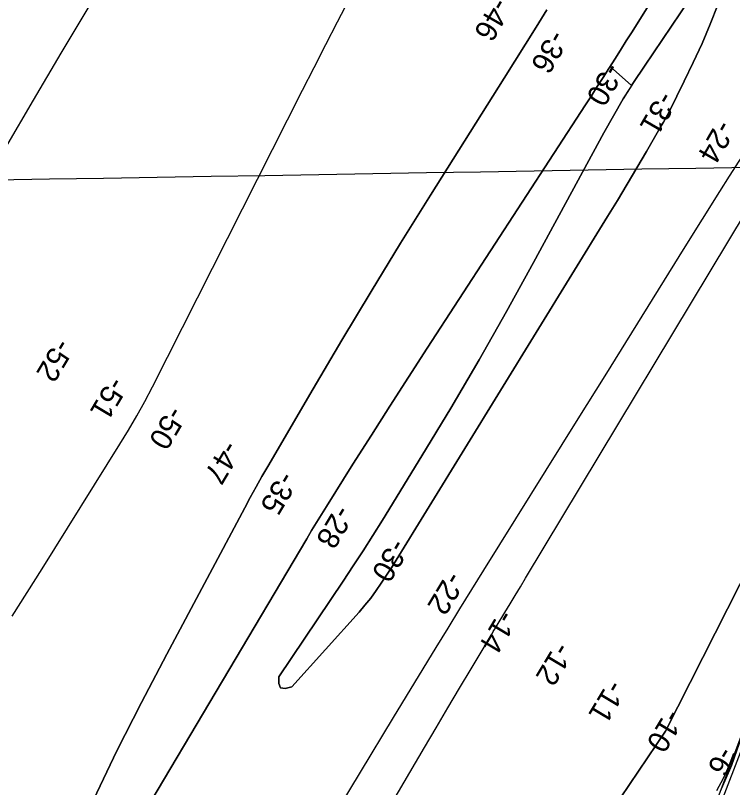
# Model space of a CAD drawing. Extents: x 3888273 to 3909528, y 158682 to 181032.
# Drawn here: x 3899572 to 3900681, y 167939 to 169134 of the extents above; entities that cross this region are included whole.
import ezdxf

# ---------------------------------------------------------------- set-up
doc = ezdxf.new("R2010")
doc.units = 0
for name, color, linetype in [('V-GRID-MAJR', 7, 'Continuous'), ('V-RIVR-JETY', 7, 'Continuous'), ('V-RIVR-RANG', 7, 'Continuous'), ('V-RRAP-FSHR', 7, 'Continuous'), ('V-TOPO-DPTH', 7, 'Continuous'), ('V-TOPO-MAJR', 7, 'Continuous'), ('V-TOPO-MINR', 7, 'Continuous'), ('V-WETL-SWMP', 7, 'Continuous')]:
    doc.layers.add(name, color=color, linetype=linetype)

msp = doc.modelspace()

# ---------------------------------------------------------------- linework, layer by layer
at = {"layer": 'V-GRID-MAJR'}
msp.add_spline([(3893488.4, 168777.6), (3893877.7, 168784.1), (3899208, 168873.7), (3904538.3, 168964), (3905476.7, 168980)], degree=3, dxfattribs=at)
at = {"layer": 'V-RIVR-JETY'}
msp.add_lwpolyline([(3900652.2, 167887.9), (3900673.8, 167944.1), (3900699.3, 168009.2), (3900716.3, 168058), (3900715.7, 168061.2), (3900711.4, 168062), (3900709.8, 168060.9), (3900706.6, 168053.2), (3900678.9, 167973.2), (3900661.4, 167933.3)], dxfattribs=at)
at = {"layer": 'V-RRAP-FSHR'}
msp.add_lwpolyline([(3899996.7, 166588.8), (3900029.7, 166643.4), (3900051.8, 166695.8), (3900145, 166878), (3900473, 167514.6), (3900528.8, 167603.3), (3900571.9, 167693.2), (3900769.5, 168220.1), (3900854, 168410.1), (3901111.7, 168921.3), (3901230.8, 169130.1), (3901232.3, 169133), (3901298.6, 169231.8), (3901395, 169369.5), (3901586, 169601.1), (3901720.2, 169757.4), (3901855.1, 169965.2), (3902076, 170299.4), (3902258.6, 170576), (3902394.3, 170771.7), (3902466.4, 170877.4)], dxfattribs=at)
at = {"layer": 'V-TOPO-DPTH'}
for points in [[(3899237.6, 166978.5), (3899631, 167664.9), (3900022.2, 168324.2), (3900029.7, 168336.7), (3900037.2, 168349.1), (3900044.8, 168361.5), (3900052.5, 168373.8), (3900093.7, 168439.4), (3900122.1, 168484.4), (3900150.6, 168529.3), (3900179.4, 168574.1), (3900208.3, 168618.8), (3900453.3, 168995.5), (3900462.4, 169009.6), (3900471.5, 169023.7), (3900480.5, 169037.8), (3900489.5, 169051.9), (3900498.5, 169066.1), (3900507.4, 169080.2), (3900516.3, 169094.4), (3900525.2, 169108.6), (3900898, 169705.4)], [(3900898, 169705.4), (3900525.2, 169108.6), (3900516.3, 169094.4), (3900507.4, 169080.2), (3900498.5, 169066.1), (3900491.3, 169054.7), (3900524.6, 169025.3)], [(3901523.7, 169550.8), (3901139.1, 169059.9), (3900979.7, 168809.1), (3900964.5, 168784.3), (3900949.7, 168759.3), (3900935.7, 168733.8), (3900922.2, 168708), (3900577.1, 168026.2), (3900117.9, 167345.7), (3899775.5, 166667.7), (3899771.7, 166626.4)], [(3900054.5, 167878.4), (3900105.3, 167962.9), (3900156.4, 168047.4), (3900222.4, 168155.8), (3900240.7, 168185.8), (3900259.1, 168215.9), (3900277.6, 168245.8), (3900296.2, 168275.7), (3900442, 168509.9), (3900483.4, 168576.4), (3900524.8, 168642.9), (3900566.2, 168709.4), (3900607.6, 168775.8), (3900660.8, 168861.2), (3900675.8, 168884.9), (3900690.9, 168908.5), (3900706.4, 168931.9), (3900722.1, 168955.1), (3901022.7, 169328.3)], [(3900054.5, 167878.4), (3900105.3, 167962.9), (3900156.4, 168047.4), (3900222.4, 168155.8), (3900240.7, 168185.8), (3900259.1, 168215.9), (3900277.6, 168245.8), (3900296.2, 168275.7), (3900442, 168509.9), (3900483.4, 168576.4), (3900524.8, 168642.9), (3900566.2, 168709.4), (3900607.6, 168775.8), (3900660.8, 168861.2), (3900675.8, 168884.9), (3900690.9, 168908.5), (3900706.4, 168931.9), (3900722.1, 168955.1), (3901022.7, 169328.3)], [(3900655.6, 169220.6), (3900544.3, 169055.5), (3900527.7, 169030.2), (3900511.6, 169004.5), (3900496.3, 168978.3), (3900481.4, 168951.9), (3900372.9, 168751.4), (3900331.1, 168675.9), (3900288.6, 168600.8), (3900244.9, 168526.3), (3900200.3, 168452.4), (3900139.4, 168353.1), (3900124.6, 168329.2), (3900109.6, 168305.5)], [(3900524.6, 169025.3), (3900527.7, 169030.2), (3900544.3, 169055.5), (3900655.6, 169220.6)], [(3900658.1, 169150), (3900646, 169120.1), (3900633.4, 169090.4), (3900619.9, 169061.1), (3900605.9, 169032), (3900583, 168985.9), (3900580, 168980), (3900577, 168974.2), (3900573.8, 168968.5), (3900570.5, 168962.8), (3900547.5, 168923.4), (3900532.7, 168898.1), (3900517.6, 168872.9), (3900502.5, 168847.7), (3900487.2, 168822.7), (3900156.3, 168284.4), (3900154.6, 168281.8), (3900153, 168279.2), (3900151.3, 168276.6), (3900149.6, 168273.9), (3900137.5, 168255.4), (3900129.4, 168243.8), (3900121.1, 168232.4), (3900112.2, 168221.4), (3900103, 168210.7), (3899999, 168094.8), (3899988.9, 168092.2), (3899981.7, 168093.3), (3899978.9, 168100), (3899978.9, 168110.5), (3900078.7, 168258.6), (3900094.2, 168282), (3900109.6, 168305.5)], [(3900109.6, 168305.5), (3900094.2, 168282), (3900078.7, 168258.6), (3899978.9, 168110.5), (3899978.9, 168100), (3899981.7, 168093.3), (3899988.9, 168092.2), (3899999, 168094.8), (3900103, 168210.7), (3900112.2, 168221.4), (3900121.1, 168232.4), (3900129.4, 168243.8), (3900137.5, 168255.4), (3900149.6, 168273.9), (3900151.3, 168276.6), (3900153, 168279.2), (3900154.6, 168281.8), (3900156.3, 168284.4), (3900487.2, 168822.7), (3900502.5, 168847.7), (3900517.6, 168872.9), (3900532.7, 168898.1), (3900547.5, 168923.4), (3900570.5, 168962.8), (3900573.8, 168968.5), (3900577, 168974.2), (3900580, 168980), (3900583, 168985.9), (3900605.9, 169032), (3900619.9, 169061.1), (3900633.4, 169090.4), (3900646, 169120.1), (3900658.1, 169150)], [(3900393.3, 169142.3), (3900377, 169115.8), (3900360.5, 169089.4), (3900344, 169063), (3900327.5, 169036.7), (3900213.7, 168855.8), (3900167.4, 168781.3), (3900121.6, 168706.6), (3900076.5, 168631.4), (3900031.9, 168555.9), (3899962, 168436.1), (3899952.8, 168420.2), (3899943.8, 168404.2), (3899934.9, 168388.1), (3899926.2, 168372), (3899805.6, 168145.6), (3899766.7, 168071), (3899728.7, 167995.9), (3899692.2, 167920.1)], [(3899692.2, 167920.1), (3899728.7, 167995.9), (3899766.7, 168071), (3899805.6, 168145.6), (3899926.2, 168372), (3899934.9, 168388.1), (3899943.8, 168404.2), (3899952.8, 168420.2), (3899962, 168436.1), (3900031.9, 168555.9), (3900076.5, 168631.4), (3900121.6, 168706.6), (3900167.4, 168781.3), (3900213.7, 168855.8), (3900327.5, 169036.7), (3900344, 169063), (3900360.5, 169089.4), (3900377, 169115.8), (3900393.3, 169142.3)], [(3900523.2, 169023), (3900524.6, 169025.3), (3900491.3, 169054.7), (3900490, 169052.7), (3900489.5, 169051.9), (3900480.5, 169037.8), (3900471.5, 169023.7), (3900462.4, 169009.6), (3900453.3, 168995.5), (3900208.3, 168618.8), (3900179.4, 168574.1), (3900150.6, 168529.3), (3900122.1, 168484.4), (3900093.7, 168439.4), (3900052.5, 168373.8), (3900044.8, 168361.5), (3900037.2, 168349.1), (3900029.7, 168336.7), (3900022.2, 168324.2), (3899631, 167664.9), (3899237.6, 166978.5), (3899234.6, 166973.7), (3899231.7, 166968.9), (3898895.1, 166384.7)], [(3900109.6, 168305.5), (3900124.6, 168329.2), (3900139.4, 168353.1), (3900200.3, 168452.4), (3900244.9, 168526.3), (3900288.6, 168600.8), (3900331.1, 168675.9), (3900372.9, 168751.4), (3900481.4, 168951.9), (3900496.3, 168978.3), (3900511.6, 169004.5), (3900523.2, 169023)]]:
    msp.add_lwpolyline(points, dxfattribs=at)
at = {"layer": 'V-TOPO-MAJR'}
for points in [[(3899566.7, 168204.1), (3899613, 168277.6), (3899733.3, 168470.2), (3899746.6, 168492.1), (3899759.4, 168514.2), (3899771.7, 168536.7), (3899783.6, 168559.3), (3900015.8, 169017.9), (3900033.7, 169053.3), (3900051.6, 169088.6), (3900069.6, 169123.9), (3900087.6, 169159.2)], [(3899685.2, 169147.8), (3899642.1, 169075.2), (3899599.1, 169002.5), (3899556.4, 168929.6)]]:
    msp.add_lwpolyline(points, dxfattribs=at)
at = {"layer": 'V-TOPO-MINR'}
for points in [[(3899237.6, 166978.5), (3899631, 167664.9), (3900022.2, 168324.2), (3900029.7, 168336.7), (3900037.2, 168349.1), (3900044.8, 168361.5), (3900052.5, 168373.8), (3900093.7, 168439.4), (3900122.1, 168484.4), (3900150.6, 168529.3), (3900179.4, 168574.1), (3900208.3, 168618.8), (3900453.3, 168995.5), (3900462.4, 169009.6), (3900471.5, 169023.7), (3900480.5, 169037.8), (3900489.5, 169051.9), (3900498.5, 169066.1), (3900507.4, 169080.2), (3900516.3, 169094.4), (3900525.2, 169108.6), (3900898, 169705.4)], [(3899771.7, 166626.4), (3899775.5, 166667.7), (3900117.9, 167345.7), (3900577.1, 168026.2), (3900922.2, 168708), (3900935.7, 168733.8), (3900949.7, 168759.3), (3900964.5, 168784.3), (3900979.7, 168809.1), (3901139.1, 169059.9), (3901523.7, 169550.8)], [(3900054.5, 167878.4), (3900105.3, 167962.9), (3900156.4, 168047.4), (3900222.4, 168155.8), (3900240.7, 168185.8), (3900259.1, 168215.9), (3900277.6, 168245.8), (3900296.2, 168275.7), (3900442, 168509.9), (3900483.4, 168576.4), (3900524.8, 168642.9), (3900566.2, 168709.4), (3900607.6, 168775.8), (3900660.8, 168861.2), (3900675.8, 168884.9), (3900690.9, 168908.5), (3900706.4, 168931.9), (3900722.1, 168955.1), (3901022.7, 169328.3)], [(3900655.6, 169220.6), (3900544.3, 169055.5), (3900527.7, 169030.2), (3900511.6, 169004.5), (3900496.3, 168978.3), (3900481.4, 168951.9), (3900372.9, 168751.4), (3900331.1, 168675.9), (3900288.6, 168600.8), (3900244.9, 168526.3), (3900200.3, 168452.4), (3900139.4, 168353.1), (3900124.6, 168329.2), (3900109.6, 168305.5)], [(3900109.6, 168305.5), (3900094.2, 168282), (3900078.7, 168258.6), (3899978.9, 168110.5), (3899978.9, 168100), (3899981.7, 168093.3), (3899988.9, 168092.2), (3899999, 168094.8), (3900103, 168210.7), (3900112.2, 168221.4), (3900121.1, 168232.4), (3900129.4, 168243.8), (3900137.5, 168255.4), (3900149.6, 168273.9), (3900151.3, 168276.6), (3900153, 168279.2), (3900154.6, 168281.8), (3900156.3, 168284.4), (3900487.2, 168822.7), (3900502.5, 168847.7), (3900517.6, 168872.9), (3900532.7, 168898.1), (3900547.5, 168923.4), (3900570.5, 168962.8), (3900573.8, 168968.5), (3900577, 168974.2), (3900580, 168980), (3900583, 168985.9), (3900605.9, 169032), (3900619.9, 169061.1), (3900633.4, 169090.4), (3900646, 169120.1), (3900658.1, 169150)], [(3899692.2, 167920.1), (3899728.7, 167995.9), (3899766.7, 168071), (3899805.6, 168145.6), (3899926.2, 168372), (3899934.9, 168388.1), (3899943.8, 168404.2), (3899952.8, 168420.2), (3899962, 168436.1), (3900031.9, 168555.9), (3900076.5, 168631.4), (3900121.6, 168706.6), (3900167.4, 168781.3), (3900213.7, 168855.8), (3900327.5, 169036.7), (3900344, 169063), (3900360.5, 169089.4), (3900377, 169115.8), (3900393.3, 169142.3)], [(3899919.7, 167516), (3900204.3, 168001.3), (3900222.3, 168031.8), (3900240.3, 168062.3), (3900258.3, 168092.7), (3900276.4, 168123.1), (3900308.7, 168177.2), (3900310.7, 168180.5), (3900312.7, 168183.9), (3900314.7, 168187.3), (3900316.8, 168190.6), (3900328.6, 168210.2), (3900336.6, 168223.4), (3900344.6, 168236.5), (3900352.5, 168249.7), (3900360.4, 168262.9), (3900731.2, 168878.7)]]:
    msp.add_lwpolyline(points, dxfattribs=at)
at = {"layer": 'V-WETL-SWMP'}
for p, q in [((3900675.5, 167973.2), (3900682.6, 167992.4)), ((3900666.6, 167953.9), (3900675.5, 167973.2)), ((3900656.4, 167934.6), (3900666.6, 167953.9))]:
    msp.add_line(p, q, dxfattribs=at)

# ---------------------------------------------------------------- texts
at = {"layer": 'V-RIVR-RANG'}
for s, rotation, p in [('-46', 240.0287, (3900312.2, 169163.4)), ('-36', 240.0287, (3900400.2, 169113.4)), ('-30', 240.0287, (3900485.7, 169063.1)), ('-31', 239.8883, (3900568.4, 169018.5)), ('-24', 239.8883, (3900658.3, 168974.3)), ('-52', 239.1892, (3899635.9, 168636)), ('-51', 239.1892, (3899719, 168576.9)), ('-50', 239.1892, (3899810, 168531.5)), ('-47', 239.1892, (3899894.9, 168478.1)), ('-35', 239.1892, (3899982.2, 168430.5)), ('-28', 239.1892, (3900068.7, 168378.2)), ('-30', 239.0483, (3900154.6, 168326.5)), ('-22', 239.0483, (3900240.8, 168275.8)), ('-14', 239.0483, (3900321.6, 168216.1)), ('-12', 239.0483, (3900408.3, 168166.1)), ('-11', 239.0483, (3900489.9, 168107.8)), ('-10', 239.0483, (3900579.6, 168062.9)), ('-6', 239.0483, (3900661.3, 168004.8))]:
    msp.add_text(s, height=33.5, rotation=rotation, dxfattribs=at).set_placement(p)

doc.saveas('drawing.dxf')
